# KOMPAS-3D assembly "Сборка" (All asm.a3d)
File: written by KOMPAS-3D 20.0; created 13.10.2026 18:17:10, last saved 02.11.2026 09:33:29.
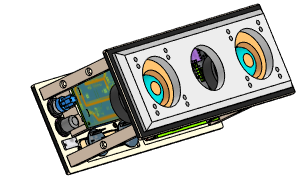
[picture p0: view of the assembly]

Document properties: Полное имя файла: D:\RicWork\Project-EPS32\box_compas\All asm.a3d

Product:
- Part/product: Сборка
    Масса: 3.1999
  - Component [detail]: Деталь  | Масса: 0.00678464; source file: переключатели и кнопки\Индикатор емкости литиевой батареи GBL 18650.m3d
  - Component [assembly]: Сборка  | Масса: 1.6131; source file: корпус\корпус v1 asm.a3d
  - Component [assembly]: Сборка  | Масса: 1.58002; source file: сборки компонентов\Back_Panel_Сборка_v3.a3d

Referenced files in D:\RicWork\Project-EPS32\box_compas\корпус\: корпус v1 asm.a3d
Referenced files in D:\RicWork\Project-EPS32\box_compas\сборки компонентов\: Back_Panel_Сборка_v3.a3d
Referenced files in D:\RicWork\Project-EPS32\box_compas\переключатели и кнопки\: Индикатор емкости литиевой батареи GBL 18650.m3d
